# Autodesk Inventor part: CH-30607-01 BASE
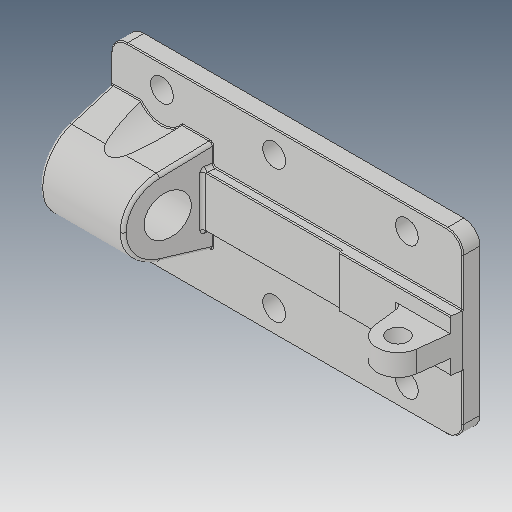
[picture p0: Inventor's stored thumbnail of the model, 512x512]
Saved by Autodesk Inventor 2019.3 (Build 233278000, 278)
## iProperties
Created: 2012-09
Part Number: CH-30607-01 BASE
Material: Ogólny
Document SubType Name: Modeling
Designer: CADENGINEERING4
Density: 1 g/cm^3
Appearance: Domyślna
Author: CADENGINEERING4
Revision Number: ÈÎºÎ
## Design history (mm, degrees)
feature "Ô²½Ç7"
node "Bryła1"
